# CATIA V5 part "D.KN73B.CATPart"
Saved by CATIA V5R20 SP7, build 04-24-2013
Part number: D.KN73B
Material "Nessuno"
Bounding box of the stored display mesh (mm): x -30.572 to 150.807, y -143.683 to 0, z -91.151 to 75.737
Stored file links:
  C:\Users\designer2\Desktop\Ottobre 2022\25-10-2022\04\Yori Evo 48V\D.KN73B.CATPart
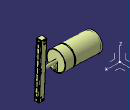
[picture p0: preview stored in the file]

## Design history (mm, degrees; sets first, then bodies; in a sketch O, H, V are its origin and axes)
AxisSystem1: origin (0, 0, 0), X (1, 0, 0), Y (0, 1, 0), Z (0, 0, 1)
Set1
  DatumSurface1
Body1 (main body), material "Nessuno"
